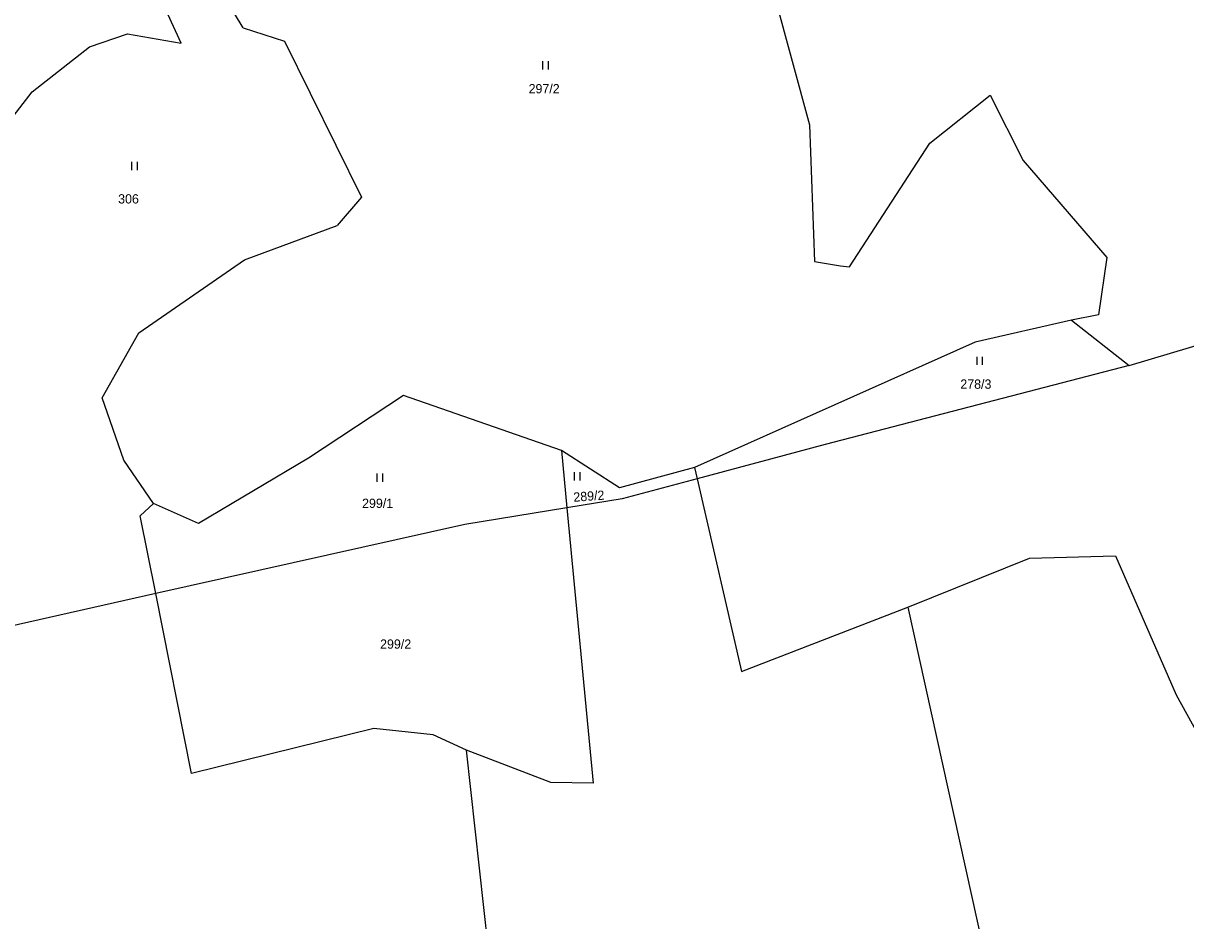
# Model space of a CAD drawing. Extents: x -645290 to -643454, y -1064771 to -1062356.
# Drawn here: x -644337.3 to -644124.4, y -1063831.9 to -1063667.6 of the extents above; entities that cross this region are included whole.
import ezdxf

# ---------------------------------------------------------------- set-up
doc = ezdxf.new("R2010")
doc.units = 0
doc.header["$LTSCALE"] = 0.68
doc.layers.add('1', color=7, linetype='Continuous', lineweight=25)
doc.layers.add('3', color=7, linetype='Continuous', lineweight=25)
doc.layers.add('2', color=7, linetype='Continuous')

msp = doc.modelspace()

# ---------------------------------------------------------------- linework, layer by layer
at = {"layer": '1'}
for p, q in [((-644308.43, -1063671.28), (-644321, -1063643.72)), ((-644205.13, -1063643.13), (-644193.31, -1063686.18)), ((-644297.05, -1063668.47), (-644308.72, -1063648.86)), ((-644325.2, -1063671.93), (-644318.23, -1063669.52)), ((-644318.23, -1063669.52), (-644308.43, -1063671.28)), ((-644297.05, -1063668.47), (-644289.48, -1063670.88)), ((-644335.66, -1063680.17), (-644325.2, -1063671.93)), ((-644289.48, -1063670.88), (-644275.38, -1063699.44)), ((-644345.2, -1063692.39), (-644335.66, -1063680.17)), ((-644171.31, -1063689.54), (-644160.28, -1063680.78)), ((-644160.28, -1063680.78), (-644154.22, -1063692.72)), ((-644193.31, -1063686.18), (-644192.4, -1063711.19)), ((-644186.04, -1063712.19), (-644171.31, -1063689.54)), ((-644154.22, -1063692.72), (-644138.91, -1063710.48)), ((-644275.38, -1063699.44), (-644279.81, -1063704.65)), ((-644296.78, -1063710.9), (-644279.81, -1063704.65)), ((-644138.91, -1063710.48), (-644140.43, -1063720.99)), ((-644316.18, -1063724.25), (-644296.78, -1063710.9)), ((-644192.4, -1063711.19), (-644187.65, -1063711.99)), ((-644187.65, -1063711.99), (-644186.04, -1063712.19)), ((-644140.43, -1063720.99), (-644145.37, -1063721.95)), ((-644145.37, -1063721.95), (-644163.01, -1063725.97)), ((-644145.37, -1063721.95), (-644134.8, -1063730.27)), ((-644322.85, -1063736.19), (-644316.18, -1063724.25)), ((-644134.8, -1063730.27), (-644117.85, -1063725.22)), ((-644163.01, -1063725.97), (-644214.37, -1063748.96)), ((-644134.8, -1063730.27), (-644190.48, -1063744.73)), ((-644318.91, -1063747.56), (-644322.85, -1063736.19)), ((-644267.71, -1063735.74), (-644285.1, -1063747.24)), ((-644238.77, -1063745.83), (-644267.71, -1063735.74)), ((-644190.48, -1063744.73), (-644213.9, -1063751)), ((-644238.77, -1063745.83), (-644237.77, -1063756.31)), ((-644228.16, -1063752.65), (-644238.77, -1063745.83)), ((-644313.45, -1063755.51), (-644318.91, -1063747.56)), ((-644285.1, -1063747.24), (-644305.25, -1063759.18)), ((-644214.37, -1063748.96), (-644228.16, -1063752.65)), ((-644214.37, -1063748.96), (-644213.9, -1063751)), ((-644213.9, -1063751), (-644227.62, -1063754.67)), ((-644213.9, -1063751), (-644205.77, -1063786.28)), ((-644227.62, -1063754.67), (-644237.77, -1063756.31)), ((-644315.88, -1063757.79), (-644313.45, -1063755.51)), ((-644305.25, -1063759.18), (-644313.45, -1063755.51)), ((-644237.77, -1063756.31), (-644256.48, -1063759.34)), ((-644237.77, -1063756.31), (-644232.96, -1063806.74)), ((-644313.05, -1063772), (-644315.88, -1063757.79)), ((-644256.48, -1063759.34), (-644313.05, -1063772)), ((-644175.31, -1063774.49), (-644153.03, -1063765.54)), ((-644153.03, -1063765.54), (-644137.28, -1063765.11)), ((-644137.28, -1063765.11), (-644126.21, -1063790.55)), ((-644313.05, -1063772), (-644364.63, -1063783.55)), ((-644306.48, -1063804.96), (-644313.05, -1063772)), ((-644205.77, -1063786.28), (-644175.31, -1063774.49)), ((-644175.31, -1063774.49), (-644147.42, -1063900.81)), ((-644126.21, -1063790.55), (-644119.09, -1063803.48)), ((-644273.14, -1063796.72), (-644306.48, -1063804.96)), ((-644262.23, -1063797.86), (-644273.14, -1063796.72)), ((-644256.17, -1063800.7), (-644262.23, -1063797.86)), ((-644241.61, -1063932.75), (-644256.17, -1063800.7)), ((-644240.68, -1063806.6), (-644256.17, -1063800.7)), ((-644232.96, -1063806.74), (-644240.68, -1063806.6))]:
    msp.add_line(p, q, dxfattribs=at)
at = {"layer": '3'}
for p, q in [((-644242.161, -1063676.05), (-644242.161, -1063674.55)), ((-644241.16, -1063676.05), (-644241.16, -1063674.55)), ((-644317.421, -1063694.5), (-644317.421, -1063693)), ((-644316.42, -1063694.5), (-644316.42, -1063693)), ((-644162.631, -1063730.15), (-644162.631, -1063728.65)), ((-644161.63, -1063730.15), (-644161.63, -1063728.65)), ((-644272.481, -1063751.55), (-644272.481, -1063750.05)), ((-644271.48, -1063751.55), (-644271.48, -1063750.05)), ((-644236.351, -1063751.31), (-644236.351, -1063749.81)), ((-644235.35, -1063751.31), (-644235.35, -1063749.81))]:
    msp.add_line(p, q, dxfattribs=at)

# ---------------------------------------------------------------- texts
at = {"layer": '2'}
for s, p in [('297/2', (-644244.78, -1063680.435)), ('306', (-644319.94, -1063700.604)), ('278/3', (-644165.72, -1063734.515)), ('299/1', (-644275.27, -1063756.334)), ('299/2', (-644271.97, -1063782.104))]:
    msp.add_text(s, height=1.7, dxfattribs=at).set_placement(p)
msp.add_text('289/2', height=1.7, rotation=4, dxfattribs=at).set_placement((-644236.52, -1063755.213))

doc.saveas('drawing.dxf')
